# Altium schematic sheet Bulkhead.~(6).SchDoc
size B; Organization: Monterey Bay Aquarium Research Institute; Address1: 7700 Sandholdt Rd; Address2: Moss Landing, CA 95039-9644; CompanyName: MBARI
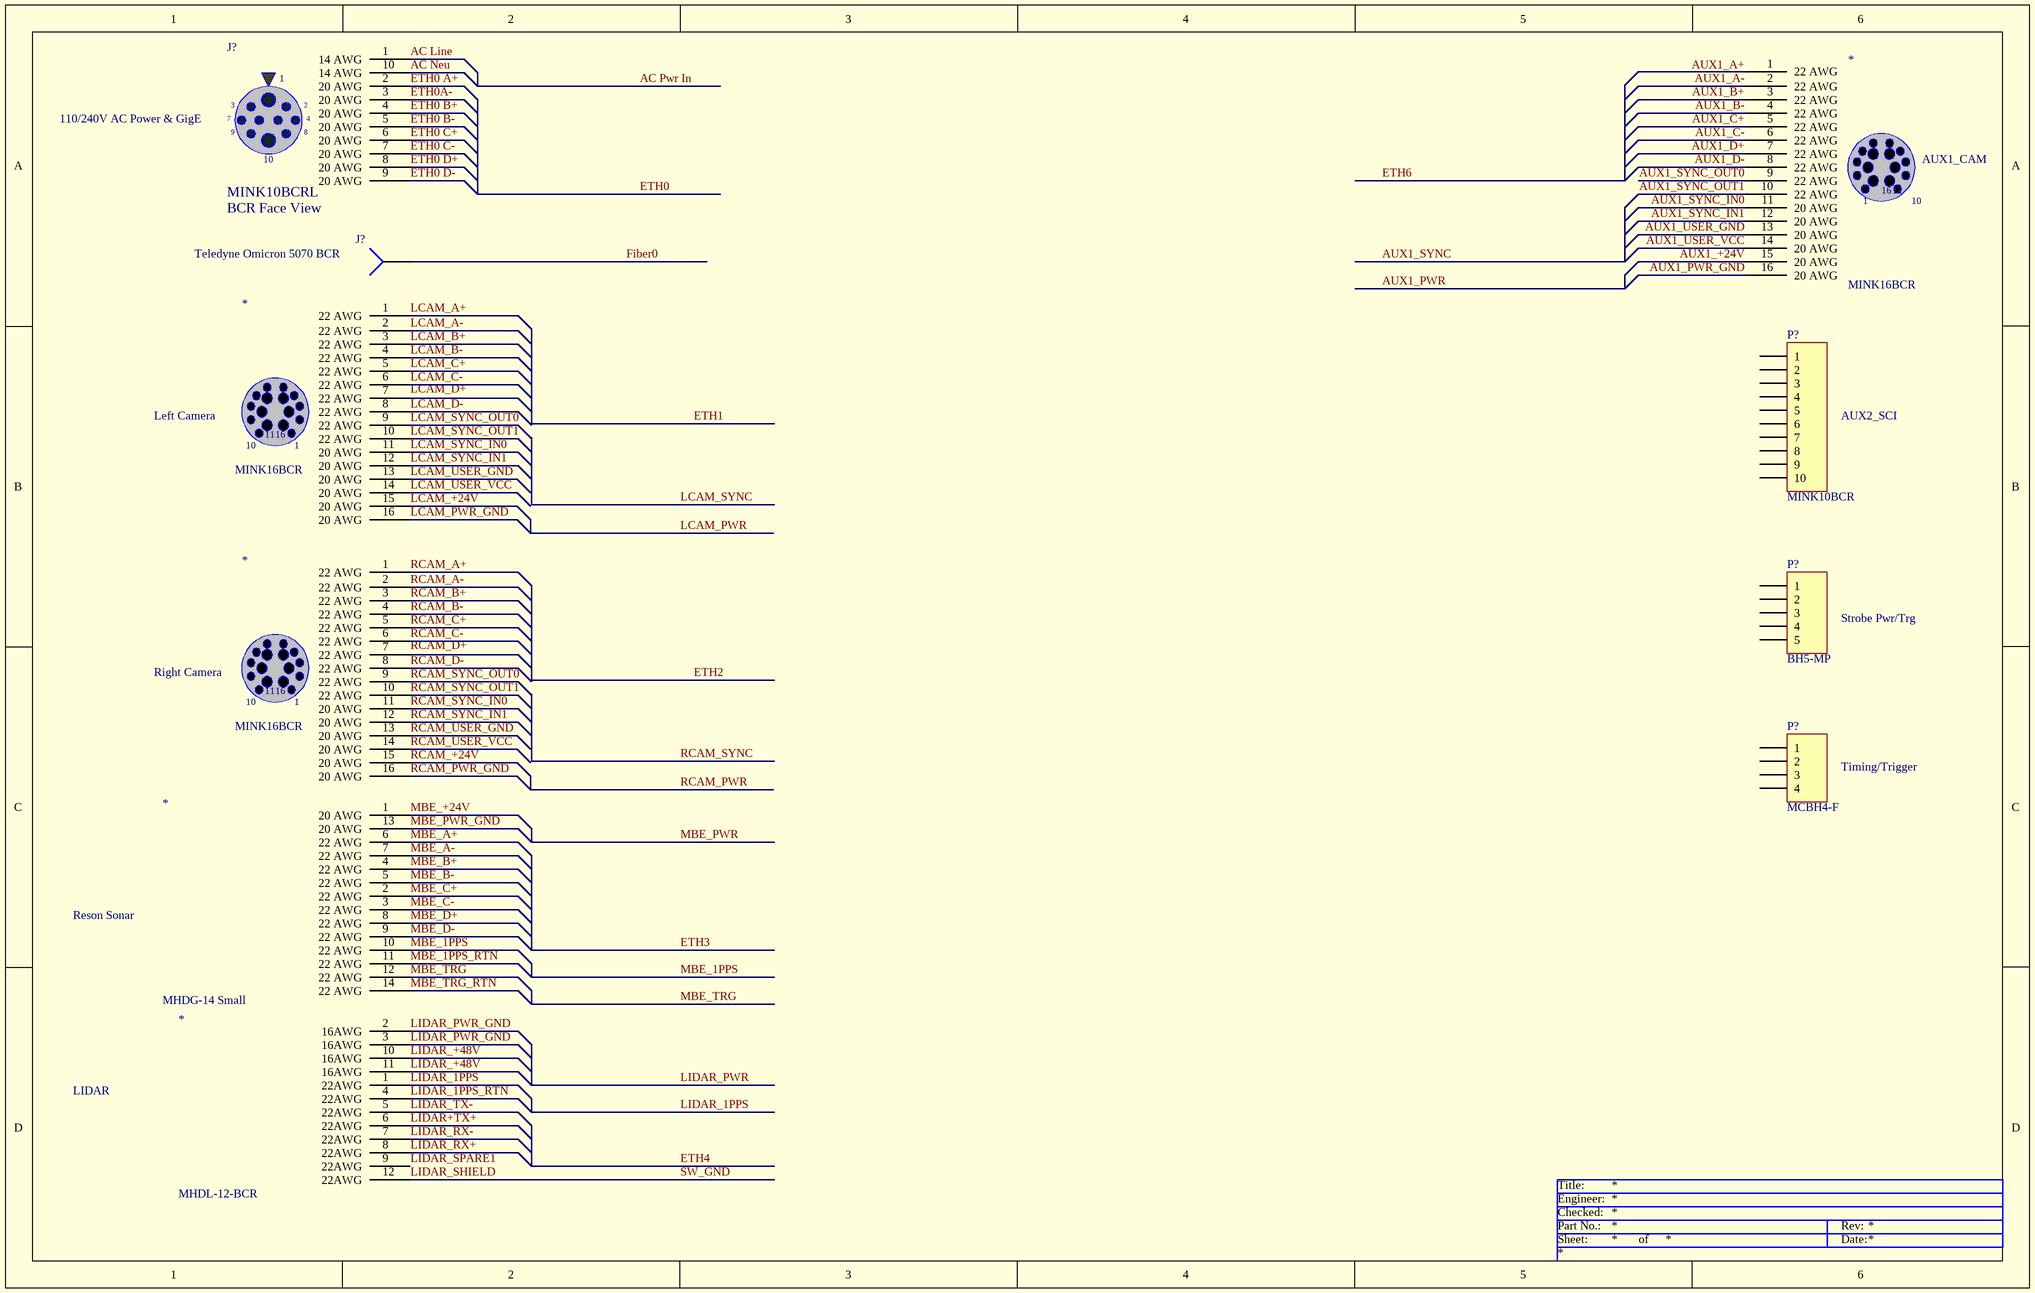
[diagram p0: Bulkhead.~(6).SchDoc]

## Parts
(Parts that share a designator on the sheet are numbered #1, #2 ... from top to bottom, then left to right.)
*#1  MINK16BCR
*#2  MINK16BCR
*#3  MINK16BCR
*#4  MHDG-14 Small
*#5  MHDL-12-BCR
J?#1  MINK10BCRL  View: BCR Face View
J?#2  Teledyne Omicron 5070 BCR  [PIN1]
P?#1  MINK10BCR  [HDR1X10]
P?#2  BH5-MP  [HDR1X5]
P?#3  MCBH4-F  [HDR1X4]

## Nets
AC Line: J?#1.1(14_AWG)
AC Neu: J?#1.10(14_AWG)
AUX1_+24V: *#1.15(20_AWG)
AUX1_A-: *#1.2(22_AWG)
AUX1_B+: *#1.3(22_AWG)
AUX1_B-: *#1.4(22_AWG)
AUX1_C+: *#1.5(22_AWG)
AUX1_C-: *#1.6(22_AWG)
AUX1_D+: *#1.7(22_AWG)
AUX1_D-: *#1.8(22_AWG)
AUX1_PWR_GND: *#1.16(20_AWG)
AUX1_SYNC_IN0: *#1.11(20_AWG)
AUX1_SYNC_IN1: *#1.12(20_AWG)
AUX1_SYNC_OUT0: *#1.9(22_AWG)
AUX1_SYNC_OUT1: *#1.10(22_AWG)
AUX1_USER_GND: *#1.13(20_AWG)
AUX1_USER_VCC: *#1.14(20_AWG)
ETH0 A+: J?#1.2(20_AWG)
ETH0 B+: J?#1.4(20_AWG)
ETH0 B-: J?#1.5(20_AWG)
ETH0 C+: J?#1.6(20_AWG)
ETH0 C-: J?#1.7(20_AWG)
ETH0 D+: J?#1.8(20_AWG)
ETH0 D-: J?#1.9(20_AWG)
ETH0A-: J?#1.3(20_AWG)
Fiber0: J?#2.1
LCAM_+24V: *#2.15(20_AWG)
LCAM_A+: *#2.1(22_AWG)
LCAM_A-: *#2.2(22_AWG)
LCAM_B+: *#2.3(22_AWG)
LCAM_B-: *#2.4(22_AWG)
LCAM_C+: *#2.5(22_AWG)
LCAM_C-: *#2.6(22_AWG)
LCAM_D-: *#2.8(22_AWG)
LCAM_PWR_GND: *#2.16(20_AWG)
LCAM_SYNC_IN0: *#2.11(20_AWG)
LCAM_SYNC_IN1: *#2.12(20_AWG)
LCAM_SYNC_OUT0: *#2.9(22_AWG)
LCAM_SYNC_OUT1: *#2.10(22_AWG)
LCAM_USER_GND: *#2.13(20_AWG)
LCAM_USER_VCC: *#2.14(20_AWG)
LIDAR+TX+: *#5.6(22AWG)
LIDAR_1PPS: *#5.1(22AWG)
LIDAR_1PPS_RTN: *#5.4(22AWG)
LIDAR_+48V: *#5.10(16AWG) *#5.11(16AWG)
LIDAR_PWR_GND: *#5.2(16AWG) *#5.3(16AWG)
LIDAR_RX+: *#5.8(22AWG)
LIDAR_RX-: *#5.7(22AWG)
LIDAR_SHIELD: *#5.12(22AWG)  [also labelled SW_GND]
LIDAR_SPARE1: *#5.9(22AWG)
LIDAR_TX-: *#5.5(22AWG)
MBE_1PPS: *#4.10(22_AWG)
MBE_1PPS_RTN: *#4.11(22_AWG)
MBE_+24V: *#4.1(20_AWG)
MBE_A+: *#4.6(22_AWG)
MBE_A-: *#4.7(22_AWG)
MBE_B+: *#4.4(22_AWG)
MBE_B-: *#4.5(22_AWG)
MBE_C+: *#4.2(22_AWG)
MBE_C-: *#4.3(22_AWG)
MBE_D+: *#4.8(22_AWG)
MBE_D-: *#4.9(22_AWG)
MBE_PWR_GND: *#4.13(20_AWG)
MBE_TRG: *#4.12(22_AWG)
MBE_TRG_RTN: *#4.14(22_AWG)
RCAM_+24V: *#3.15(20_AWG)
RCAM_A+: *#3.1(22_AWG)
RCAM_A-: *#3.2(22_AWG)
RCAM_B+: *#3.3(22_AWG)
RCAM_B-: *#3.4(22_AWG)
RCAM_C+: *#3.5(22_AWG)
RCAM_C-: *#3.6(22_AWG)
RCAM_D-: *#3.8(22_AWG)
RCAM_PWR_GND: *#3.16(20_AWG)
RCAM_SYNC_IN0: *#3.11(20_AWG)
RCAM_SYNC_IN1: *#3.12(20_AWG)
RCAM_SYNC_OUT0: *#3.9(22_AWG)
RCAM_SYNC_OUT1: *#3.10(22_AWG)
RCAM_USER_GND: *#3.13(20_AWG)
RCAM_USER_VCC: *#3.14(20_AWG)

Not connected (* = marked no-connect by the designer): *#1 1(22_AWG); *#2 7(22_AWG); *#3 7(22_AWG); P?#1 1 2 3 4 5 6 7 8 9 10; P?#2 1 2 3 4 5; P?#3 1 2 3 4

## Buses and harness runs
bus AC Pwr In
bus AUX1_PWR
bus AUX1_SYNC
bus ETH0
bus ETH1
bus ETH2
bus ETH3
bus ETH4
bus ETH6
bus LCAM_PWR
bus LCAM_SYNC
bus LIDAR_1PPS
bus LIDAR_PWR
bus MBE_1PPS
bus MBE_PWR
bus MBE_TRG
bus RCAM_PWR
bus RCAM_SYNC

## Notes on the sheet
- 110/240V AC Power & GigE
- AUX1_CAM
- Left Camera
- AUX2_SCI
- Strobe Pwr/Trg
- Right Camera
- Timing/Trigger
- Reson Sonar
- LIDAR
- Labels drawn without touching a wire or pin: AUX1_A+, LCAM_D+, RCAM_D+

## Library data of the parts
*#1-*#3 = SEACON-MINK-16-FCR: Seacon MINK-16 FCR
*#5 = MHDL-12-BCR: Impulse MHDL12 BCR
J?#1 = SEACON-MINK-10/L CCR (SMALL): Seacon MINK-10/L-CCR Molded to C/F Falmat Cable
J?#2 = Socket
P?#1 = Header 10: Header, 10-Pin
P?#2 = Header 5: Header, 5-Pin
P?#3 = Header 4: Header, 4-Pin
